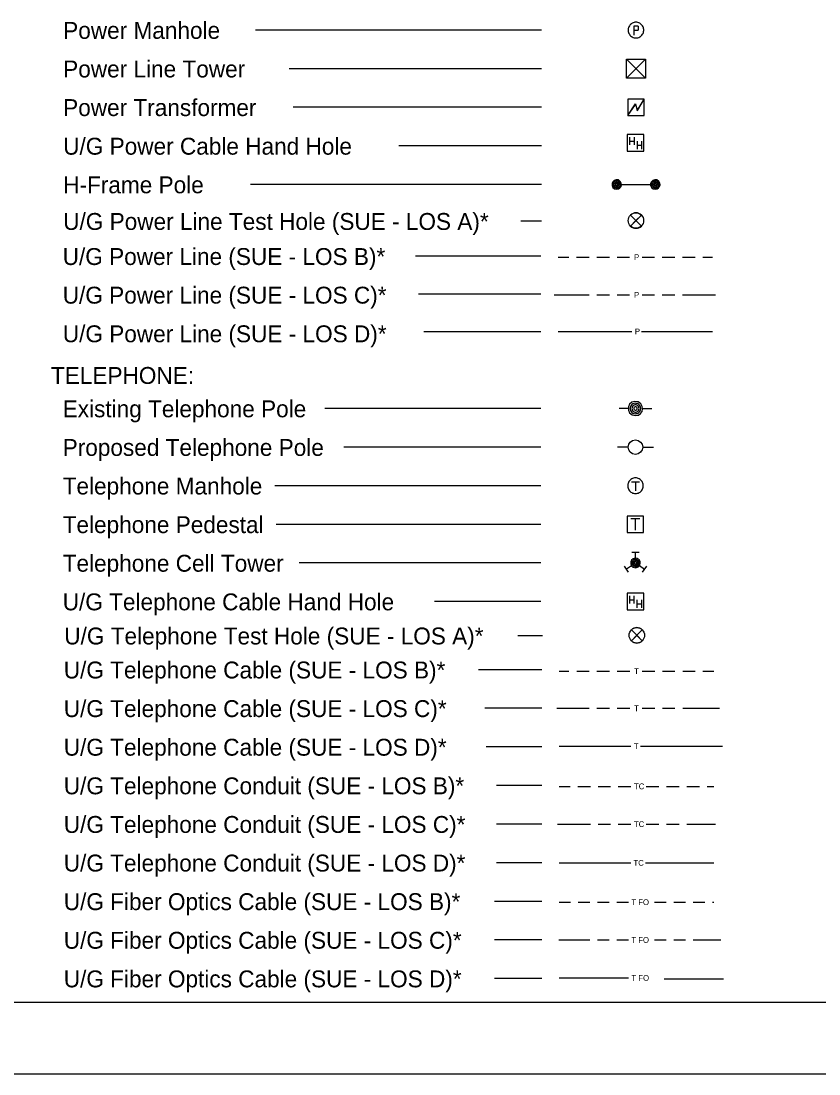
# Model space of a CAD drawing. Extents: x -0.53 to 3.34, y -0.27 to 4.33.
# Drawn here: x 1.661 to 2.356, y 2.495 to 3.412 of the extents above; entities that cross this region are included whole.
import ezdxf

# ---------------------------------------------------------------- set-up
doc = ezdxf.new("R2010")
doc.units = 0
for name, color, linetype in [('Exist Utilities Power Test Hole SUE LOS A CELL', 7, 'Continuous'), ('Exist Utilities Telephone Test Hole SUE LOS A CELL', 7, 'Continuous'), ('Sheet_Plan', 7, 'Continuous'), ('Sheet_Symbology', 7, 'Continuous'), ('z - Construction', 7, 'Continuous')]:
    doc.layers.add(name, color=color, linetype=linetype)

msp = doc.modelspace()

# ---------------------------------------------------------------- linework, layer by layer
at = {"layer": 'Exist Utilities Power Test Hole SUE LOS A CELL'}
for points in [[(2.20097, 3.24322), (2.19146, 3.23372), (2.19621, 3.23847), (2.19146, 3.24322), (2.20097, 3.23372)], [(2.19146, 3.24322), (2.19621, 3.23847), (2.20097, 3.24322)], [(2.20097, 3.23372), (2.19621, 3.23847), (2.19146, 3.23372)]]:
    msp.add_lwpolyline(points, dxfattribs=at)
msp.add_circle((2.19621, 3.23847), 0.00672, dxfattribs=at)
for start, end in [(45, 135), (225, 315)]:
    msp.add_arc((2.19621, 3.23847), 0.00672, start, end, dxfattribs=at)
at = {"layer": 'Exist Utilities Telephone Test Hole SUE LOS A CELL'}
for points in [[(2.20176, 2.88193), (2.19226, 2.87243), (2.19701, 2.87718), (2.19226, 2.88193), (2.20176, 2.87243)], [(2.19226, 2.88193), (2.19701, 2.87718), (2.20176, 2.88193)], [(2.20176, 2.87243), (2.19701, 2.87718), (2.19226, 2.87243)]]:
    msp.add_lwpolyline(points, dxfattribs=at)
msp.add_circle((2.19701, 2.87718), 0.00672, dxfattribs=at)
for start, end in [(45, 135), (225, 315)]:
    msp.add_arc((2.19701, 2.87718), 0.00672, start, end, dxfattribs=at)
at = {"layer": 'Sheet_Plan'}
msp.add_line((0.2799, 2.55761), (2.98819, 2.55761), dxfattribs=at)
at = {"layer": 'Sheet_Symbology'}
for p, q in [((2.11384, 3.40438), (1.8647, 3.40438)), ((2.19762, 3.40405), (2.19456, 3.40405)), ((2.19817, 3.40749), (2.19817, 3.4046)), ((2.20469, 3.37919), (2.1879, 3.36239)), ((2.20469, 3.36239), (2.1879, 3.37919)), ((2.11384, 3.37075), (1.89411, 3.37075)), ((2.11384, 3.33712), (1.89752, 3.33712)), ((2.19075, 3.31121), (2.19075, 3.30443)), ((2.19462, 3.31121), (2.19462, 3.30443)), ((2.11384, 3.30349), (1.98958, 3.30349)), ((2.19075, 3.30775), (2.19462, 3.30775)), ((2.19722, 3.30752), (2.19722, 3.30074)), ((2.19722, 3.30406), (2.20109, 3.30406)), ((2.20109, 3.30752), (2.20109, 3.30074)), ((2.11384, 3.26986), (1.86044, 3.26986)), ((2.17944, 3.26986), (2.21307, 3.26986)), ((2.11384, 3.23795), (2.09595, 3.23795)), ((2.11338, 3.2074), (2.00421, 3.2074)), ((2.12853, 3.20657), (2.13778, 3.20657)), ((2.14451, 3.20657), (2.15544, 3.20657)), ((2.16216, 3.20657), (2.17309, 3.20657)), ((2.17982, 3.20657), (2.19075, 3.20657)), ((2.20151, 3.20657), (2.21244, 3.20657)), ((2.21917, 3.20657), (2.2301, 3.20657)), ((2.23682, 3.20657), (2.24775, 3.20657)), ((2.25448, 3.20657), (2.26306, 3.20657)), ((2.11338, 3.17441), (2.0068, 3.17441)), ((2.12513, 3.17377), (2.15544, 3.17377)), ((2.16216, 3.17377), (2.17309, 3.17377)), ((2.17982, 3.17377), (2.19075, 3.17377)), ((2.20151, 3.17377), (2.21244, 3.17377)), ((2.21917, 3.17377), (2.2301, 3.17377)), ((2.23682, 3.17377), (2.26546, 3.17377)), ((2.11338, 3.14142), (2.01132, 3.14142)), ((2.12853, 3.14189), (2.19258, 3.14189)), ((2.20099, 3.14189), (2.26306, 3.14189)), ((2.11338, 3.07474), (1.92523, 3.07474)), ((2.18959, 3.07474), (2.18152, 3.07474)), ((2.202, 3.07474), (2.21007, 3.07474)), ((2.11338, 3.04111), (1.94175, 3.04111)), ((2.18955, 3.04109), (2.18009, 3.04109)), ((2.20216, 3.04109), (2.21162, 3.04109)), ((2.19929, 3.01065), (2.19235, 3.01065)), ((2.19579, 3.01065), (2.19579, 3.003)), ((2.11338, 3.00748), (1.88155, 3.00748)), ((2.11338, 2.97385), (1.88273, 2.97385)), ((2.19186, 2.97892), (2.19973, 2.97892)), ((2.19579, 2.96878), (2.19579, 2.97892)), ((2.19264, 2.94974), (2.19895, 2.94974)), ((2.19579, 2.94436), (2.19579, 2.94974)), ((2.11338, 2.94022), (1.9028, 2.94022)), ((2.18982, 2.93218), (2.1862, 2.93735)), ((2.19242, 2.93785), (2.18801, 2.93477)), ((2.19919, 2.93786), (2.20359, 2.93477)), ((2.2054, 2.93736), (2.20178, 2.93219)), ((2.19064, 2.91168), (2.19064, 2.9049)), ((2.19064, 2.90822), (2.19451, 2.90822)), ((2.19451, 2.91168), (2.19451, 2.9049)), ((2.19711, 2.90798), (2.19711, 2.90121)), ((2.20098, 2.90798), (2.20098, 2.90121)), ((2.11338, 2.90659), (2.02083, 2.90659)), ((2.19711, 2.90453), (2.20098, 2.90453)), ((2.11475, 2.87686), (2.09347, 2.87686)), ((2.11429, 2.84723), (2.05917, 2.84723)), ((2.12945, 2.84589), (2.1379, 2.84589)), ((2.14463, 2.84589), (2.15556, 2.84589)), ((2.16228, 2.84589), (2.17321, 2.84589)), ((2.17994, 2.84589), (2.19087, 2.84589)), ((2.20163, 2.84589), (2.21256, 2.84589)), ((2.21929, 2.84589), (2.23022, 2.84589)), ((2.23694, 2.84589), (2.24787, 2.84589)), ((2.2546, 2.84589), (2.26398, 2.84589)), ((2.11429, 2.8136), (2.06448, 2.8136)), ((2.12735, 2.8136), (2.15556, 2.8136)), ((2.16228, 2.8136), (2.17321, 2.8136)), ((2.17994, 2.8136), (2.19087, 2.8136)), ((2.20163, 2.8136), (2.21256, 2.8136)), ((2.21929, 2.8136), (2.23022, 2.8136)), ((2.23694, 2.8136), (2.26896, 2.8136)), ((2.11429, 2.77997), (2.06577, 2.77997)), ((2.12945, 2.78056), (2.19188, 2.78056)), ((2.20029, 2.78056), (2.27155, 2.78056)), ((2.11429, 2.74634), (2.07484, 2.74634)), ((2.12945, 2.74562), (2.13885, 2.74562)), ((2.14557, 2.74562), (2.1565, 2.74562)), ((2.16323, 2.74562), (2.17416, 2.74562)), ((2.18088, 2.74562), (2.19181, 2.74562)), ((2.20527, 2.74562), (2.2162, 2.74562)), ((2.22292, 2.74562), (2.23385, 2.74562)), ((2.24058, 2.74562), (2.25151, 2.74562)), ((2.25824, 2.74562), (2.26398, 2.74562)), ((2.11429, 2.71271), (2.07484, 2.71271)), ((2.12785, 2.71271), (2.1565, 2.71271)), ((2.16323, 2.71271), (2.17416, 2.71271)), ((2.18088, 2.71271), (2.19181, 2.71271)), ((2.20527, 2.71271), (2.2162, 2.71271)), ((2.22292, 2.71271), (2.23385, 2.71271)), ((2.24058, 2.71271), (2.26559, 2.71271)), ((2.11429, 2.67908), (2.07484, 2.67908)), ((2.12945, 2.67899), (2.19181, 2.67899)), ((2.20443, 2.67899), (2.26398, 2.67899)), ((2.11429, 2.64544), (2.07289, 2.64544)), ((2.12945, 2.64471), (2.13927, 2.64471)), ((2.14599, 2.64471), (2.15608, 2.64471)), ((2.16281, 2.64471), (2.1729, 2.64471)), ((2.17962, 2.64471), (2.18971, 2.64471)), ((2.21241, 2.64471), (2.2225, 2.64471)), ((2.22923, 2.64471), (2.23932, 2.64471)), ((2.24605, 2.64471), (2.25613, 2.64471)), ((2.26286, 2.64471), (2.26398, 2.64471)), ((2.11429, 2.61181), (2.07289, 2.61181)), ((2.12914, 2.61181), (2.15608, 2.61181)), ((2.16281, 2.61181), (2.1729, 2.61181)), ((2.17962, 2.61181), (2.18971, 2.61181)), ((2.21241, 2.61181), (2.2225, 2.61181)), ((2.22923, 2.61181), (2.23932, 2.61181)), ((2.24605, 2.61181), (2.27011, 2.61181)), ((2.11429, 2.57818), (2.07289, 2.57818)), ((2.12945, 2.57873), (2.18978, 2.57873)), ((2.22088, 2.57809), (2.27238, 2.57809))]:
    msp.add_line(p, q, dxfattribs=at)
for points in [[(2.19625, 3.41121), (2.19538, 3.41115), (2.19456, 3.41099), (2.19374, 3.41072), (2.19298, 3.41033), (2.19227, 3.4099), (2.19161, 3.40935), (2.19101, 3.4087), (2.19052, 3.40804), (2.19008, 3.40728), (2.18981, 3.40646), (2.18959, 3.40564), (2.18948, 3.40482), (2.18948, 3.40394), (2.18959, 3.40312), (2.18981, 3.40225), (2.19008, 3.40148), (2.19052, 3.40072), (2.19101, 3.40007), (2.19161, 3.39941), (2.19227, 3.39886), (2.19298, 3.39843), (2.19374, 3.39805), (2.19456, 3.39777), (2.19543, 3.39761), (2.19625, 3.39755), (2.19713, 3.39761), (2.19795, 3.39777), (2.19877, 3.39805), (2.19953, 3.39843), (2.20024, 3.39886), (2.2009, 3.39941), (2.2015, 3.40007), (2.20199, 3.40072), (2.20243, 3.40148), (2.2027, 3.4023), (2.20292, 3.40312), (2.20303, 3.40394), (2.20303, 3.40482), (2.20292, 3.40564), (2.2027, 3.40651), (2.20243, 3.40728), (2.20199, 3.40804), (2.2015, 3.4087), (2.2009, 3.40935), (2.20024, 3.4099), (2.19953, 3.41033), (2.19877, 3.41072), (2.19795, 3.41099), (2.19707, 3.41115), (2.19625, 3.41121)], [(2.19456, 3.40001), (2.19456, 3.40405), (2.19456, 3.40804), (2.19762, 3.40804)], [(2.19762, 3.40804), (2.19784, 3.40798), (2.198, 3.40788), (2.19811, 3.40771), (2.19817, 3.40749)], [(2.19817, 3.4046), (2.19811, 3.40438), (2.198, 3.40422), (2.19784, 3.40411), (2.19762, 3.40405)], [(2.20469, 3.36239), (2.1879, 3.36239), (2.1879, 3.37919), (2.20469, 3.37919), (2.20469, 3.36239), (2.1879, 3.36239), (2.1879, 3.37919), (2.20469, 3.37919), (2.20469, 3.36239)], [(2.18925, 3.33011), (2.19586, 3.33962), (2.19748, 3.33445), (2.20326, 3.34413)], [(2.18925, 3.33011), (2.19592, 3.34001), (2.19742, 3.33406), (2.20326, 3.34413)], [(2.18925, 3.33011), (2.20326, 3.33011), (2.20326, 3.34413), (2.18925, 3.34413), (2.18925, 3.33011)], [(2.18867, 3.29888), (2.20314, 3.29888), (2.20314, 3.31336), (2.18867, 3.31336), (2.18867, 3.29888)], [(2.1825, 3.26986), (2.18242, 3.2706), (2.18217, 3.27126), (2.18175, 3.27184), (2.18126, 3.27234), (2.18068, 3.27267), (2.17993, 3.27283), (2.17927, 3.27292), (2.17853, 3.27275), (2.17786, 3.2725), (2.17737, 3.27209), (2.17687, 3.27151), (2.17654, 3.27093), (2.17637, 3.27019), (2.17637, 3.26952), (2.17654, 3.26878), (2.17687, 3.2682), (2.17737, 3.26762), (2.17786, 3.26721), (2.17853, 3.26696), (2.17927, 3.26679), (2.17993, 3.26688), (2.18068, 3.26704), (2.18126, 3.26737), (2.18175, 3.26787), (2.18217, 3.26845), (2.18242, 3.26911), (2.1825, 3.26986)], [(2.18151, 3.26986), (2.18142, 3.27044), (2.18117, 3.27101), (2.18076, 3.27143), (2.18027, 3.27176), (2.17977, 3.27192), (2.17911, 3.27192), (2.17861, 3.27176), (2.17811, 3.27143), (2.1777, 3.27101), (2.17745, 3.27044), (2.17737, 3.26986), (2.17745, 3.26928), (2.1777, 3.2687), (2.17811, 3.26828), (2.17861, 3.26795), (2.17911, 3.26779), (2.17977, 3.26779), (2.18027, 3.26795), (2.18076, 3.26828), (2.18117, 3.2687), (2.18142, 3.26928), (2.18151, 3.26986)], [(2.18043, 3.26986), (2.18035, 3.27027), (2.1801, 3.2706), (2.17977, 3.27077), (2.17936, 3.27085), (2.17894, 3.27068), (2.17861, 3.27044), (2.17844, 3.27002), (2.17844, 3.26969), (2.17861, 3.26928), (2.17894, 3.26903), (2.17936, 3.26886), (2.17977, 3.26894), (2.1801, 3.26911), (2.18035, 3.26944), (2.18043, 3.26986)], [(2.21613, 3.26986), (2.21605, 3.2706), (2.2158, 3.27126), (2.21539, 3.27184), (2.21489, 3.27234), (2.21431, 3.27267), (2.21356, 3.27283), (2.2129, 3.27292), (2.21216, 3.27275), (2.2115, 3.2725), (2.211, 3.27209), (2.21051, 3.27151), (2.21017, 3.27093), (2.21001, 3.27019), (2.21001, 3.26952), (2.21017, 3.26878), (2.21051, 3.2682), (2.211, 3.26762), (2.2115, 3.26721), (2.21216, 3.26696), (2.2129, 3.26679), (2.21356, 3.26688), (2.21431, 3.26704), (2.21489, 3.26737), (2.21539, 3.26787), (2.2158, 3.26845), (2.21605, 3.26911), (2.21613, 3.26986)], [(2.21514, 3.26986), (2.21505, 3.27044), (2.21481, 3.27101), (2.21439, 3.27143), (2.2139, 3.27176), (2.2134, 3.27192), (2.21274, 3.27192), (2.21224, 3.27176), (2.21174, 3.27143), (2.21133, 3.27101), (2.21108, 3.27044), (2.211, 3.26986), (2.21108, 3.26928), (2.21133, 3.2687), (2.21174, 3.26828), (2.21224, 3.26795), (2.21274, 3.26779), (2.2134, 3.26779), (2.2139, 3.26795), (2.21439, 3.26828), (2.21481, 3.2687), (2.21505, 3.26928), (2.21514, 3.26986)], [(2.21406, 3.26986), (2.21398, 3.27027), (2.21373, 3.2706), (2.2134, 3.27077), (2.21299, 3.27085), (2.21257, 3.27068), (2.21224, 3.27044), (2.21208, 3.27002), (2.21208, 3.26969), (2.21224, 3.26928), (2.21257, 3.26903), (2.21299, 3.26886), (2.2134, 3.26894), (2.21373, 3.26911), (2.21398, 3.26944), (2.21406, 3.26986)], [(2.20039, 3.07474), (2.20026, 3.07586), (2.19989, 3.07685), (2.19927, 3.07772), (2.19852, 3.07847), (2.19766, 3.07897), (2.19654, 3.07921), (2.19554, 3.07934), (2.19443, 3.07909), (2.19343, 3.07872), (2.19269, 3.0781), (2.19195, 3.07723), (2.19145, 3.07636), (2.1912, 3.07524), (2.1912, 3.07425), (2.19145, 3.07313), (2.19195, 3.07226), (2.19269, 3.07139), (2.19343, 3.07077), (2.19443, 3.0704), (2.19554, 3.07015), (2.19654, 3.07028), (2.19766, 3.07052), (2.19852, 3.07102), (2.19927, 3.07177), (2.19989, 3.07264), (2.20026, 3.07363), (2.20039, 3.07474)], [(2.1989, 3.07474), (2.19877, 3.07561), (2.1984, 3.07648), (2.19778, 3.0771), (2.19704, 3.0776), (2.19629, 3.07785), (2.1953, 3.07785), (2.19455, 3.0776), (2.19381, 3.0771), (2.19319, 3.07648), (2.19282, 3.07561), (2.19269, 3.07474), (2.19282, 3.07387), (2.19319, 3.07301), (2.19381, 3.07239), (2.19455, 3.07189), (2.1953, 3.07164), (2.19629, 3.07164), (2.19704, 3.07189), (2.19778, 3.07239), (2.1984, 3.07301), (2.19877, 3.07387), (2.1989, 3.07474)], [(2.19728, 3.07474), (2.19716, 3.07536), (2.19679, 3.07586), (2.19629, 3.07611), (2.19567, 3.07623), (2.19505, 3.07599), (2.19455, 3.07561), (2.1943, 3.07499), (2.1943, 3.07449), (2.19455, 3.07387), (2.19505, 3.0735), (2.19567, 3.07325), (2.19629, 3.07338), (2.19679, 3.07363), (2.19716, 3.07412), (2.19728, 3.07474)], [(2.19579, 3.01431), (2.19492, 3.01425), (2.1941, 3.01409), (2.19328, 3.01382), (2.19252, 3.01343), (2.19181, 3.013), (2.19115, 3.01245), (2.19055, 3.0118), (2.19006, 3.01114), (2.18962, 3.01038), (2.18935, 3.00956), (2.18913, 3.00874), (2.18902, 3.00792), (2.18902, 3.00704), (2.18913, 3.00623), (2.18935, 3.00535), (2.18962, 3.00459), (2.19006, 3.00382), (2.19055, 3.00317), (2.19115, 3.00251), (2.19181, 3.00197), (2.19252, 3.00153), (2.19328, 3.00115), (2.1941, 3.00087), (2.19497, 3.00071), (2.19579, 3.00066), (2.19667, 3.00071), (2.19749, 3.00087), (2.19831, 3.00115), (2.19907, 3.00153), (2.19978, 3.00197), (2.20044, 3.00251), (2.20104, 3.00317), (2.20153, 3.00382), (2.20197, 3.00459), (2.20224, 3.00541), (2.20246, 3.00623), (2.20257, 3.00704), (2.20257, 3.00792), (2.20246, 3.00874), (2.20224, 3.00961), (2.20197, 3.01038), (2.20153, 3.01114), (2.20104, 3.0118), (2.20044, 3.01245), (2.19978, 3.013), (2.19907, 3.01343), (2.19831, 3.01382), (2.19749, 3.01409), (2.19661, 3.01425), (2.19579, 3.01431)], [(2.18872, 2.96677), (2.20287, 2.96677), (2.20287, 2.98093), (2.18872, 2.98093), (2.18872, 2.96677)], [(2.19886, 2.94022), (2.19877, 2.94096), (2.19852, 2.94163), (2.19811, 2.94221), (2.19761, 2.9427), (2.19704, 2.94303), (2.19629, 2.9432), (2.19563, 2.94328), (2.19488, 2.94312), (2.19422, 2.94287), (2.19373, 2.94245), (2.19323, 2.94187), (2.1929, 2.94129), (2.19273, 2.94055), (2.19273, 2.93989), (2.1929, 2.93914), (2.19323, 2.93856), (2.19373, 2.93798), (2.19422, 2.93757), (2.19488, 2.93732), (2.19563, 2.93716), (2.19629, 2.93724), (2.19704, 2.9374), (2.19761, 2.93774), (2.19811, 2.93823), (2.19852, 2.93881), (2.19877, 2.93948), (2.19886, 2.94022)], [(2.19786, 2.94022), (2.19778, 2.9408), (2.19753, 2.94138), (2.19712, 2.94179), (2.19662, 2.94212), (2.19613, 2.94229), (2.19546, 2.94229), (2.19497, 2.94212), (2.19447, 2.94179), (2.19406, 2.94138), (2.19381, 2.9408), (2.19373, 2.94022), (2.19381, 2.93964), (2.19406, 2.93906), (2.19447, 2.93865), (2.19497, 2.93832), (2.19546, 2.93815), (2.19613, 2.93815), (2.19662, 2.93832), (2.19712, 2.93865), (2.19753, 2.93906), (2.19778, 2.93964), (2.19786, 2.94022)], [(2.19679, 2.94022), (2.1967, 2.94063), (2.19646, 2.94096), (2.19613, 2.94113), (2.19571, 2.94121), (2.1953, 2.94105), (2.19497, 2.9408), (2.1948, 2.94039), (2.1948, 2.94005), (2.19497, 2.93964), (2.1953, 2.93939), (2.19571, 2.93923), (2.19613, 2.93931), (2.19646, 2.93948), (2.1967, 2.93981), (2.19679, 2.94022)], [(2.18856, 2.89935), (2.20303, 2.89935), (2.20303, 2.91383), (2.18856, 2.91383), (2.18856, 2.89935)]]:
    msp.add_lwpolyline(points, dxfattribs=at)
for points in [[(2.17944, 3.26572), (2.18117, 3.26605), (2.18233, 3.26688), (2.18325, 3.26804), (2.18358, 3.26961), (2.18341, 3.2711), (2.18258, 3.27259), (2.18093, 3.27383), (2.17902, 3.27399), (2.17737, 3.2735), (2.17605, 3.27234), (2.17538, 3.27077), (2.17538, 3.26894), (2.17605, 3.26737), (2.17753, 3.26613)], [(2.21307, 3.26572), (2.21481, 3.26605), (2.21597, 3.26688), (2.21688, 3.26804), (2.21721, 3.26961), (2.21704, 3.2711), (2.21621, 3.27259), (2.21456, 3.27383), (2.21266, 3.27399), (2.211, 3.2735), (2.20968, 3.27234), (2.20901, 3.27077), (2.20901, 3.26894), (2.20968, 3.26737), (2.21117, 3.26613)], [(2.19579, 3.06854), (2.1984, 3.06903), (2.20014, 3.07028), (2.20151, 3.07202), (2.202, 3.07437), (2.20175, 3.07661), (2.20051, 3.07884), (2.19803, 3.0807), (2.19517, 3.08095), (2.19269, 3.08021), (2.19071, 3.07847), (2.18971, 3.07611), (2.18971, 3.07338), (2.19071, 3.07102), (2.19294, 3.06916)], [(2.19579, 2.93608), (2.19753, 2.93641), (2.19869, 2.93724), (2.1996, 2.9384), (2.19993, 2.93997), (2.19977, 2.94146), (2.19894, 2.94295), (2.19728, 2.94419), (2.19538, 2.94436), (2.19373, 2.94386), (2.1924, 2.9427), (2.19174, 2.94113), (2.19174, 2.93931), (2.1924, 2.93774), (2.19389, 2.93649)]]:
    msp.add_lwpolyline(points, close=True, dxfattribs=at)
msp.add_circle((2.19579, 3.04111), 0.00631, dxfattribs=at)
at = {"layer": 'z - Construction'}
msp.add_line((0.2174, 2.49511), (3.05073, 2.49511), dxfattribs=at)

# ---------------------------------------------------------------- texts
at = {"layer": 'Sheet_Symbology'}
for s, height, p in [('Power Manhole', 0.0147137, (1.69727, 3.39675)), ('Power Line Tower', 0.0147137, (1.69727, 3.36314)), ('Power Transformer', 0.0147137, (1.69725, 3.32951)), ('U/G Power Cable Hand Hole', 0.0147137, (1.69729, 3.29586)), ('H-Frame Pole', 0.0147137, (1.69729, 3.26223)), ('U/G Power Line Test Hole (SUE - LOS A)*', 0.0147137, (1.69729, 3.23032)), ('U/G Power Line (SUE - LOS B)*', 0.0147137, (1.69683, 3.19977)), ('P', 0.00504, (2.19462, 3.20405)), ('U/G Power Line (SUE - LOS C)*', 0.0147137, (1.69687, 3.16612)), ('P', 0.00504, (2.19462, 3.17125)), ('U/G Power Line (SUE - LOS D)*', 0.0147137, (1.69692, 3.13246)), ('P', 0.00504, (2.19527, 3.13937)), ('TELEPHONE:', 0.014714, (1.68664, 3.09619)), ('Existing Telephone Pole', 0.0147137, (1.69683, 3.06711)), ('Proposed Telephone Pole', 0.0147137, (1.69683, 3.03348)), ('Telephone Manhole', 0.0147137, (1.69683, 2.99985)), ('Telephone Pedestal', 0.0147137, (1.69683, 2.96622)), ('Telephone Cell Tower', 0.0147137, (1.69685, 2.93259)), ('U/G Telephone Cable Hand Hole', 0.0147137, (1.69685, 2.89896)), ('U/G Telephone Test Hole (SUE - LOS A)*', 0.0147137, (1.69823, 2.86923)), ('U/G Telephone Cable (SUE - LOS B)*', 0.0147137, (1.69777, 2.8396)), ('T', 0.00504, (2.19465, 2.84337)), ('U/G Telephone Cable (SUE - LOS C)*', 0.0147137, (1.69777, 2.80597)), ('T', 0.00504, (2.19465, 2.81108)), ('U/G Telephone Cable (SUE - LOS D)*', 0.0147137, (1.69777, 2.77234)), ('T', 0.00504, (2.19448, 2.77804)), ('U/G Telephone Conduit (SUE - LOS B)*', 0.0147137, (1.69777, 2.73871)), ('TC', 0.005045, (2.19451, 2.7431)), ('U/G Telephone Conduit (SUE - LOS C)*', 0.0147137, (1.69777, 2.70508)), ('TC', 0.005045, (2.19451, 2.71018)), ('U/G Telephone Conduit (SUE - LOS D)*', 0.0147137, (1.69777, 2.67145)), ('TC', 0.005045, (2.19409, 2.67647)), ('U/G Fiber Optics Cable (SUE - LOS B)*', 0.0147137, (1.69777, 2.63781)), ('T FO', 0.005045, (2.19224, 2.64219)), ('U/G Fiber Optics Cable (SUE - LOS C)*', 0.0147137, (1.69777, 2.60418)), ('T FO', 0.005045, (2.19224, 2.60929)), ('U/G Fiber Optics Cable (SUE - LOS D)*', 0.0147137, (1.69777, 2.57055)), ('T FO', 0.005045, (2.1923, 2.57621))]:
    msp.add_text(s, height=height, dxfattribs=at).set_placement(p)

doc.saveas('drawing.dxf')
